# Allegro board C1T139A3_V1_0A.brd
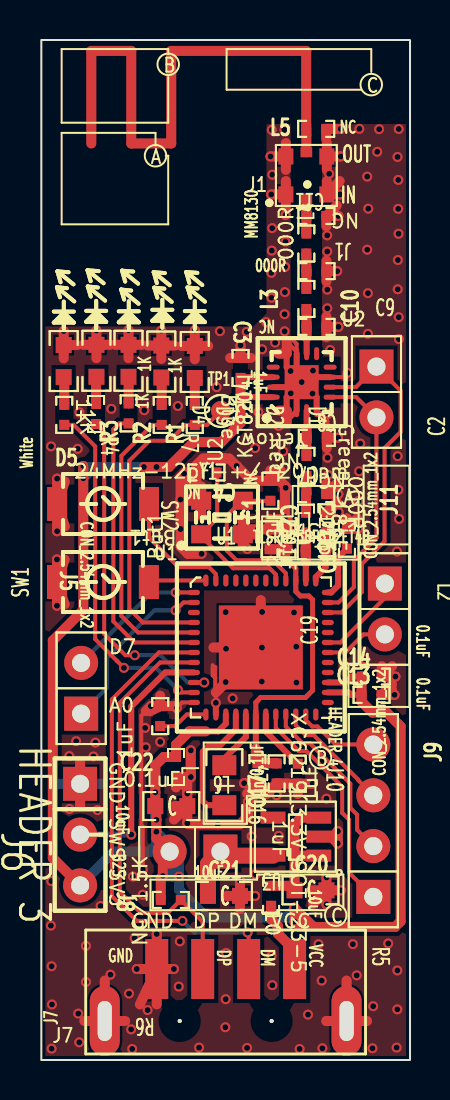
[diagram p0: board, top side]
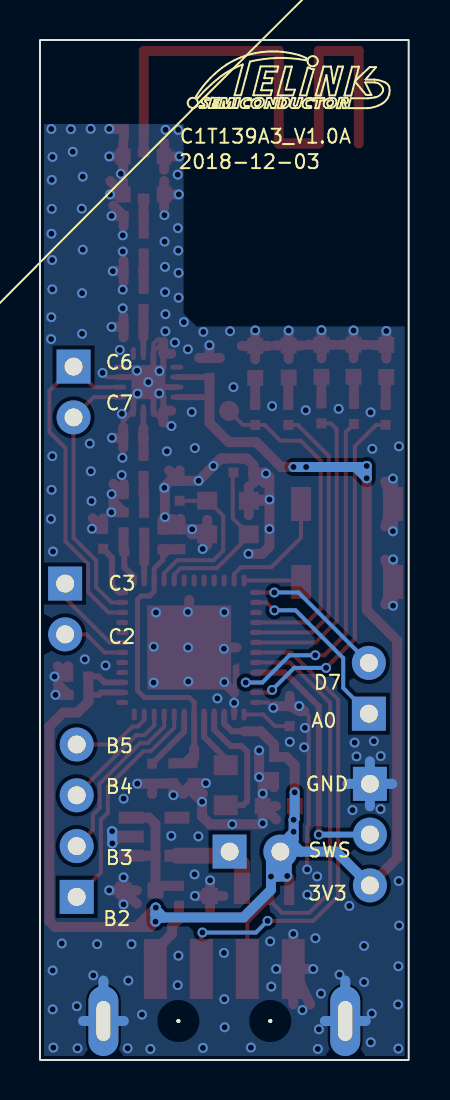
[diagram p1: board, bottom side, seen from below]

Outline 18.45 x 51 mm; copper layers: TOP, BOTTOM. Coordinates in mm from the lower left corner of the outline.
Outline path: rectangle 0,0 18.45,51

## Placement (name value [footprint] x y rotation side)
C1  NC  [0402]  11.46 28.46 90 top
C2  2.2uF  [0402]  12.31 26.03 270 top
C3  1uF  [0402]  9.97 34.6 270 top
C4  NC  [0402]  8.26 29.38 180 top
C5  18pF  [0402]  14.27 26.89 90 top
C6  220pF  [0402]  13.24 26.87 90 top
C7  NC  [0402]  13.76 28.29 180 top
C8  NC  [0402]  13.79 31.11 180 top
C9  1.5pF  [0402]  13.77 36.66 180 top
C10  1.8pF  [0402]  13.77 39.44 180 top
C11  0.5pF  [0402]  13.76 42.2 180 top
C12  1uF  [0402]  15.29 26.06 90 top
C13  0.1uF  [0402]  16.53 18.26 0 top
C14  0.1uF  [0402]  16.54 19.17 0 top
C15  1uF  [0402]  5.95 17.2 90 top
C16  1uF  [0402]  10.81 14.34 90 top
C17  0.1uF  [0402]  11.77 14.33 90 top
C18  1uF  [0402]  12.84 14.31 270 top
C19  0.1uF  [0402]  6.74 14.65 90 top
C20  10uF  [0603C]  13.47 8.48 0 top
C21  10uF  [0603C]  9.14 8.2 0 top
C22  10uF  [0603C]  6.5 12.7 0 top
C23  0.1uF  [0402]  11.42 26.04 270 top
D1  Green  [0603-LED]  7.68 34.9 90 top
D2  Red  [0603-LED]  6.01 34.92 90 top
D3  Yellow  [0603-LED]  4.36 34.96 90 top
D4  Blue  [0603-LED]  2.76 34.96 90 top
D5  White  [0603-LED]  1.12 34.95 90 top
J1  MM8130  [MM8130-2600]  13.26 44.23 180 top
J5  CON_2.54mm_1x2  [HDR254F-1X2X850]  1.99 19.86 270 top
J6  HEADER 3  [HDR254M-1X3]  1.94 13.81 270 top
J7  USB_SMT_4PIN  [USB-M-4]  9.22 4.55 90 top
J8  B2S  [HDR254F-1X2X850]  6.42 10.42 0 top
J9  CON_2.54mm_1x2  [HDR254F-1X2X850]  17.19 21.28 90 top
J10  HEADER 4  [HDR254F-1X4X850]  16.61 15.78 270 top
J11  CON_2.54mm_1x2  [HDR254F-1X2X850]  16.77 32.13 90 top
L1  1.3nH  [0402]  13.73 25.44 180 top
L2  000R  [0402]  13.27 29.71 90 top
L3  2.2nH  [0402]  13.26 38.05 90 top
L4  1.5nH  [0402]  13.26 40.82 90 top
L5  3nH  [0402]  13.75 46.56 0 top
L6  47uH  [0805L]  9.16 13.74 270 top
R1  1K  [0402]  7.68 32.25 90 top
R2  1K  [0402]  6.02 32.25 90 top
R3  1K  [0402]  4.37 32.33 90 top
R4  1K  [0402]  2.74 32.3 90 top
R5  10  [0402]  11.5 8.21 90 top
R6  NC/1.5K  [0402]  6.48 8 0 top
R7  1K  [0402]  1.15 32.26 90 top
SW1  But1  [BUTSMD2PX4_00Y3_00_NH]  3.08 23.9 270 top
SW2  But1  [BUTSMD2PX4_00Y3_00_NH]  3.09 27.8 270 top
TP1  A2  [TP100]  8.99 32.45 0 top
U1  TLSR8258F512ET48  [QFN_7X7_48PIN_0P5_4P20X4P20]  10.98 20.63 0 top
U2  KCT8204L  [QFN_3X3_16PIN_0P5_1P70X1P70]  13.03 33.89 90 top
U3  XC6219_3.3V_SOT-23-5  [SOT-23-5]  12.74 11.17 90 top
Y1  24MHz-12pF-+/-20ppm  [OSCCC200X250X080]  9.04 27.12 90 top

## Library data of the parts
C1 C4 = C1005_NC
C2 C13 C14 C23 = C1005X5R1C104K
C3 C6-C11 = C1608_NC
C5 = C1005C0G1H100D
C12 = C1608X5R1C105M
C15-C17 C19 = C1005X5R1C105K
C18 C20-C22 = C1608X5R0J106M
D1-D5 = 0603D_Red
J1 = MM8130
J5 J9 J11 = CON_2.54mm_1x2: User Part Number: pn; Tolerance: RichardLC
J6 = HEADER 3: User Part Number: pn; Tolerance: RichardLC
J7 = USB_SMT_1
J8 = B2S_0: User Part Number: pn; Tolerance: RichardLC
J10 = HEADER_4: User Part Number: pn; Tolerance: RichardLC
L1-L4 = MLK1608_000R
L5 = MLK1005S1N5ST
L6 = IND_0
R1-R4 R7 = RS0402K332JT
R5 R6 = RS0402K100JT
SW1 SW2 = SW2PIN_3x4
TP1 = TestPad100
U1 = TLSR8258F512ET48
U2 = RFX2401C_6
U3 = XC6219_1.3V_SOT-23-5
Y1 = OSC_25x32_4pin

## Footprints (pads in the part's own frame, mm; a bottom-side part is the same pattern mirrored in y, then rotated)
0402
  rect 0.5x0.5 smd: 1(-0.5,0) 2(0.5,0)
0603-LED
  rect 0.8x0.8 smd: A(-0.8,0) C(0.8,0)
0603C
  rect 0.8x0.8 smd: 1(-0.8,0) 2(0.8,0)
0805L
  rect 1x1.2 smd: 1(-1,0) 2(1,0)
BUTSMD2PX4_00Y3_00_NH
  rect 1.7x1 smd: 1(0,2.3) 2(0,-2.3)
HDR254F-1X2X850
  rect 1.7x1.7 hole 0.9: 1(2.54,0)
  round 1.7 hole 0.9: 2(0,0)
HDR254F-1X4X850
  rect 1.7x1.7 hole 0.9: 1(7.62,0)
  round 1.7 hole 0.9: 2(5.08,0) 3(2.54,0) 4(0,0)
HDR254M-1X3
  rect 1.7x1.7 hole 0.9: 1(0,0)
  round 1.7 hole 0.9: 2(2.54,0) 3(5.08,0)
MM8130-2600
  rect 0.58x0.5 smd: 1(0,1.16) 2(0,-1.16)
  rect 0.75x0.8 smd: 3(-1.025,0.95) 4(1.025,0.95) 5(-1.025,-0.95) 6(1.025,-0.95)
OSCCC200X250X080
  rect 0.9x1 smd: 1(-0.84,1.04) 2(-0.84,-1.04) 3(0.84,-1.04) 4(0.84,1.04)
QFN_3X3_16PIN_0P5_1P70X1P70
  oval 0.65x0.25 smd: 1(-1.425,0.75) 2(-1.425,0.25) 3(-1.425,-0.25) 4(-1.425,-0.75) 9(1.425,-0.75) 10(1.425,-0.25) 11(1.425,0.25) 12(1.425,0.75)
  oval 0.25x0.65 smd: 5(-0.75,-1.425) 6(-0.25,-1.425) 7(0.25,-1.425) 8(0.75,-1.425) 13(0.75,1.425) 14(0.25,1.425) 15(-0.25,1.425) 16(-0.75,1.425)
  rect 1.7x1.7 smd: 17(0,0)
QFN_7X7_48PIN_0P5_4P20X4P20
  oval 0.6x0.26 smd: 1(-3.35,2.75) 2(-3.35,2.25) 3(-3.35,1.75) 4(-3.35,1.25) 5(-3.35,0.75) 6(-3.35,0.25) 7(-3.35,-0.25) 8(-3.35,-0.75) 9(-3.35,-1.25) 10(-3.35,-1.75) 11(-3.35,-2.25) 12(-3.35,-2.75) 25(3.35,-2.75) 26(3.35,-2.25) 27(3.35,-1.75) 28(3.35,-1.25) 29(3.35,-0.75) 30(3.35,-0.25) 31(3.35,0.25) 32(3.35,0.75) 33(3.35,1.25) 34(3.35,1.75) 35(3.35,2.25) 36(3.35,2.75)
  oval 0.26x0.6 smd: 13(-2.75,-3.35) 14(-2.25,-3.35) 15(-1.75,-3.35) 16(-1.25,-3.35) 17(-0.75,-3.35) 18(-0.25,-3.35) 19(0.25,-3.35) 20(0.75,-3.35) 21(1.25,-3.35) 22(1.75,-3.35) 23(2.25,-3.35) 24(2.75,-3.35) 37(2.75,3.35) 38(2.25,3.35) 39(1.75,3.35) 40(1.25,3.35) 41(0.75,3.35) 42(0.25,3.35) 43(-0.25,3.35) 44(-0.75,3.35) 45(-1.25,3.35) 46(-1.75,3.35) 47(-2.25,3.35) 48(-2.75,3.35)
  rect 4.2x4.2 smd: 49(0,0)
SOT-23-5
  rect 0.6x1.25 smd: 1(-0.95,-1.145) 2(0,-1.145) 3(0.95,-1.145) 4(0.95,1.145) 5(-0.95,1.145)
TP100
  round 1 smd: 1(0,0)
USB-M-4
  round 0.2 hole 1.7 unplated: (-2.6,2.3) (-2.6,-2.3)
  rect 3x1.15 smd: 1(0,-3.45) 2(0,-1.15) 3(0,1.15) 4(0,3.45)
  oval 3.5x1.5 hole 2x0.7: S1(-2.6,6.05) S2(-2.6,-6.05)

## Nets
3V3: C3.2 C13.1 C14.1 C19.2 C22.1 J6.3 J8.2 R6.1 U1.15(VDD_IO) U1.26(VDD3) U1.27(VDDIO_AMS) U2.14(VDD#14) U2.16(VDD#16)
GND: C1.2 C2.1 C3.1 C4.2 C5.2 C7.1 C8.1 C9.1 C10.1 C11.1 C12.2 C13.2 C14.2 C15.2 C16.1 C17.1 C18.2 C19.1 C20.2 C21.2 C22.2 C23.1 D1.C(CATHODE) D2.C(CATHODE) D3.C(CATHODE) D4.C(CATHODE) D5.C(CATHODE) J1.3 J1.4 J1.5 J1.6 J6.1 J7.4(GND) J7.S1 J7.S2 L5.2 SW1.2 SW2.2 U1.12(DVSS#12) U1.14(DVSS#14) U1.49(GND) U2.1(BYPASS) U2.2(GND#2) U2.4(GND#4) U2.7(GND#7) U2.11(ANT_SEL) U2.12(GND#12) U2.15(GND#15) U2.17(GND#17) U3.2(VSS) Y1.2 Y1.4
VBUS: C20.1 R5.2 U3.1(VIN) U3.3(CE)
TL_1V2: C2.2 C16.2 C17.2 C23.2 U1.18(VDD1V2) U1.39(AVDD1V2)
TL_A0: J5.1 U1.2(DMIC_DI/P0N/URX/A[0])
TL_A2: R1.1 TP1.1(TP) U1.4(DO/UTX/P0/A[2])
TL_A3: R2.1 U1.5(DI/UCTS/P1/A[3])
TL_A4: R3.1 U1.6(CK/URTS/P2/A[4])
TL_ANT: C6.1 L1.2 U1.38(ANT)
TL_B0: R4.1 U1.10(P3/URX/ATSEL1/B[0])
TL_B1: R7.1 U1.11(P4/UTX/ATSEL2/B[1])
TL_B2: J10.1 U1.20(P5/UCTS/CYC2LNA/B[2])
TL_B3: J10.2 U1.21(P0N/URTS/CYC2PA/B[3])
TL_B4: J10.3 U1.22(SDMP0/P4/B[4])
TL_B5: J10.4 U1.23(SDMN0/P5/B[5])
TL_C2: J9.2 U1.30(P0/7816TRX/I2CSDA/32KO/PGAP1/C[2])
TL_C3: J9.1 U1.31(P1/URX/I2CCK/32KI/PGAN1/C[3])
TL_C6: J11.1 U1.34(CYC2LNA/ATSEL1/P4N/C[6]) U2.6(RXEN)
TL_C7: J11.2 U1.35(CYC2PA/ATSEL2/P5N/C[7]) U2.5(TXEN)
TL_D5: SW2.1 U1.47(P0/P0N/D[5])
TL_D6: SW1.1 U1.48(CN/URX/ATSEL0/D[6])
TL_D7: J5.2 U1.1(CK/I2SBCK/7816TRX/D[7])
TL_DM: J7.2(D-) U1.7(DM/A[5])
TL_DP: J7.3(D+) R6.2 U1.8(DP/A[6])
TL_SWS/A7: J6.2 U1.9(SWS/URTS/A[7])
TL_XC1: C1.1 U1.40(XC1) Y1.3
TL_XC2: C4.1 U1.41(XC2) Y1.1
N14798367: C18.1 U1.19(VDD_F)
N14798471: L6.1 U1.17(VDCDC)
N14798499: L6.2 U1.16(VDCDC_SW)
N14798557: C15.1 U1.13(VDD1V)
N14798729: C12.1 U1.36(RESETB)
N14798779: C5.1 L1.1 U1.37(VANT)
N14803016: C6.2 C7.2 L2.1
N14803042: C8.2 L2.2 U2.3(TXRX)
N14803152: C10.2 L3.2 L4.1
N14803180: C9.2 L3.1 U2.10(ANT1)
N14803220: C11.2 J1.1 L4.2
N14803264: J1.2 L5.1
N14807404: D1.A(ANODE) R1.2
N14807456: D3.A(ANODE) R3.2
N14807480: D4.A(ANODE) R4.2
N14807598: D2.A(ANODE) R2.2
N14823075: C21.1 J8.1 U3.5(VOUT)
N14823079: J7.1(5V) R5.1
N14826545: D5.A(ANODE) R7.2

Pads without a net: U1 3 24 25 28 29 32 33 42 43 44 45 46; U2 8 9 13; U3 4

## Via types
v1: diameter 0.5, hole 0.3, TOP to BOTTOM, 210 vias

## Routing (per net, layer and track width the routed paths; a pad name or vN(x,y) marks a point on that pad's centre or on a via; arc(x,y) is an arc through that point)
3V3: length 99.7
  TOP w0.3: 9.97,33.12 9.99,33.14 U2.16 ; U2.14 10.01,34.14 C3.2 ; U1.27 15.22,18.88 15.52,19.17 C14.1 ; U1.15 9.23,16.82 8.85,16.43 8.22,16.43 ; U1.26 15.39,18.38 15.51,18.26 C13.1
  TOP w0.5: C14.1 16.03,19.16 C13.1 16.03,17.92 16.57,17.37 17.29,17.37 17.98,16.68 17.98,6.94 17.7,6.65 13.62,6.65 ; 13.62,6.65 12.93,6.65 v1(12.67,6.92) 12.67,7.6 ; 13.62,6.65 12.67,7.6 ; 12.67,7.6 v1(12.65,7.62) ; C3.2 9.97,31.86 9.01,30.89 7.63,30.89 6.38,29.65 v1(5.76,29.65) v1(5.13,29.65) ; J6.3 0.58,10.09 0.58,20.97 2.1,22.5 v1(2.1,29.09) v1(2.1,29.7) ; 8.22,16.43 7.4,16.43 6.74,15.77 C19.2 6.12,15.15 5.7,14.73 v1(5.7,13.39) C22.1 5.76,12.64 v1(5.76,12.01) v1(5.76,11.41) 5.76,11.08 J8.2 6.08,10.08 v1(6.08,9.2) 5.98,9.1 R6.1
  BOTTOM w0.5: 5.76,11.39 5.76,11.08 ; 5.76,11.39 6.42,10.73 J8.2 ; 5.76,11.39 v1(5.76,11.41) v1(5.76,12.01) 5.7,12.06 v1(5.7,13.39) ; 5.76,11.08 5.76,10.76 5.41,10.42 ; 5.76,11.08 J8.2 ; 6.11,9.17 6.58,9.17 ; 6.11,9.17 6.11,10.11 J8.2 ; 6.11,9.17 v1(6.08,9.2) ; 6.58,9.17 6.42,9.33 J8.2 ; 6.58,9.17 v1(6.89,9.17) ; 2.66,29.65 v1(2.1,29.09) v1(2.1,29.7) 2.15,29.65 2.66,29.65 ; 2.66,29.65 v1(5.13,29.65) v1(5.76,29.65) ; v1(6.89,9.17) 6.89,8.51 8.27,7.13 12.27,7.13 ; v1(6.89,9.17) 6.89,9.95 J8.2 ; 12.27,7.13 12.46,7.13 v1(12.67,6.92) 12.67,7.29 ; 12.27,7.13 12.51,7.37 ; 5.41,10.42 3.63,10.42 J6.3 ; 5.41,10.42 J8.2 ; 12.67,7.29 12.6,7.29 12.51,7.37 ; 12.67,7.29 12.67,7.6 v1(12.65,7.62) 12.65,7.51 12.51,7.37
GND: length 173.8
  TOP w0.2: U1.12 7.04,17.88 v1(6.77,17.61) ; v1(15.32,34.35) 15.11,34.14 U2.7 ; U2.11 12.78,35.41 ; 12.78,35.41 12.78,35.81 12.53,36.05 ; 12.78,35.41 12.28,35.91 ; 8.69,19.66 8.7,19.65 8.7,19.1 ; 8.7,19.1 8.7,18.41 8.73,18.38 v1(8.73,17.86) ; 8.7,19.1 8.57,19.23 8.57,19.74 ; 5.23,17.44 5,17.22 5,11.74 5.08,11.66 v1(5.08,9.53)
  TOP w0.25: U2.2 12.78,32.45 12.28,31.95 ; U2.4 13.79,32.47 14.29,31.97 14.29,31.63
  TOP w0.3: U2.11 12.78,34.14 ; 12.78,34.14 12.28,34.64 U2.12 ; 12.78,34.14 U2.17 ; U1.14 v1(8.73,17.86) ; U2.4 13.78,33.14 U2.17 ; U2.17 13.28,34.14 U2.7 ; U2.17 12.78,33.64 ; U2.1 12.28,33.14 12.78,33.64 ; U2.15 12.78,33.64 ; 12.78,33.64 U2.2
  TOP w0.5: C21.2 v1(9.94,8.98) ; C21.2 9.94,7.53 ; C21.2 9.27,8.2 ; C21.2 v1(10.7,8.2) ; C23.1 11.43,26.53 C2.1 ; C23.1 11.94,27.06 ; C23.1 v1(10.83,26.54) 10.33,26.54 Y1.2 ; C23.1 11.42,27.06 ; J1.6 v1(11.47,45.18) ; J1.6 12.24,45.85 ; J1.6 12.24,44.51 ; C18.2 v1(13.58,13.81) ; C18.2 12.32,13.81 ; C18.2 12.84,13.29 ; 8,27.24 Y1.4 ; Y1.4 7.23,27.96 ; Y1.4 8,28.68 ; Y1.4 7.94,28.02 v1(6.97,28.02) ; v1(7.48,14.15) 7.3,13.97 v1(7.3,13.32) C22.2 ; v1(7.48,14.15) v1(7.48,15.48) ; v1(7.48,14.15) C19.1 ; SW2.2 1.18,28.92 ; SW2.2 v1(0.79,29.07) ; SW2.2 1.18,26.68 ; SW2.2 v1(0.79,26.44) ; 6.63,12.02 C22.2 ; C22.2 v1(7.3,11.84) 7.35,11.79 v1(8.83,11.79) 9.95,11.79 10.34,12.18 v1(10.34,12.91) 10.81,13.39 C16.1 ; C22.2 6.63,12.7 ; Y1.2 10.08,25.78 v1(10.31,25.55) ; Y1.2 10.85,26.28 ; Y1.2 10.08,27 ; SW1.2 v1(0.78,22.71) ; SW1.2 1.17,22.78 ; SW1.2 1.17,25.02 ; SW1.2 v1(0.78,25.03) ; D4.C v1(2.76,36.48) ; D4.C 2.76,35.09 ; D4.C 2.09,35.76 ; D4.C 3.43,35.76 ; v1(6.97,28.02) v1(6.97,26.55) 6.97,25.68 7.33,25.31 v1(8.02,25.31) ; v1(6.97,28.02) 6.97,29.15 v1(7.14,29.32) 7.2,29.38 C4.2 ; C5.2 14.79,27.91 ; C5.2 14.79,27.65 ; C5.2 v1(14.88,27.39) ; 6.01,35.05 D2.C ; D2.C 6.68,35.72 ; D2.C v1(6.01,36.47) ; D2.C 5.34,35.72 ; C9.1 14.27,37.18 ; C9.1 14.27,36.14 ; C9.1 v1(14.87,36.66) ; C2.1 12.05,27.05 ; C2.1 12.31,27.02 12.2,27.13 v1(12.2,27.15) 12.2,28.46 12.23,28.5 v1(12.23,28.61) 12.23,28.67 11.94,28.96 C1.2 ; C2.1 11.79,27.05 ; 13.6,8.48 C20.2 ; C20.2 13.6,7.81 ; C20.2 v1(14.27,7.78) ; C20.2 v1(14.27,9.13) ; C20.2 v1(14.99,8.48) ; 6.74,13.63 C19.1 ; C19.1 7.26,13.63 ; 7.76,28.86 C4.2 ; C4.2 7.24,28.86 ; C4.2 7.76,29.74 8.1,30.07 8.32,30.07 8.33,30.08 9.2,30.08 9.2,30.07 9.4,30.07 v1(9.77,29.7) v1(10.52,28.96) C1.2 ; 1.12,35.08 D5.C ; D5.C 1.79,35.75 ; D5.C v1(1.12,36.45) ; C1.2 11.46,29.48 ; C1.2 11.98,29.48 ; 5.78,4.55 v1(5.78,6.3) ; 5.78,4.55 5.78,2.78 ; 5.78,4.55 v1(4.78,4.55) ; 5.78,4.55 4.93,2.78 ; 5.78,4.55 v1(6.63,4.55) ; 3.69,35.76 D3.C ; D3.C 5.03,35.76 ; D3.C 4.36,35.09 ; D3.C v1(4.36,36.49) ; 14.29,44.51 J1.5 ; J1.5 v1(14.98,45.18) ; J1.5 14.29,45.85 ; C14.2 v1(17.72,19.17) ; C14.2 17.04,19.69 ; C14.2 17.56,19.69 ; D1.C 8.35,35.7 ; D1.C 7.01,35.7 ; D1.C 7.68,35.03 ; D1.C v1(7.68,36.48) ; C13.2 v1(17.67,18.26) ; C13.2 17.55,18.52 ; C13.2 17.55,18.78 ; C10.1 v1(14.8,39.44) ; C10.1 14.27,39.96 ; C10.1 14.27,38.92 ; J1.3 14.93,43.95 ; J1.3 v1(14.95,43.28) ; J1.3 14.29,43.95 ; C15.2 v1(5.48,17.7) 5.23,17.44 ; C15.2 5.95,18.22 ; C15.2 6.69,17.7 v1(6.77,17.61) ; C15.2 5.43,17.43 ; C16.1 v1(10.15,13.84) ; C16.1 11.34,13.32 ; C16.1 10.29,13.32 ; C7.1 v1(14.86,28.29) ; C7.1 14.26,28.81 ; C7.1 14.78,28.81 ; 14.29,30.59 C8.1 ; C8.1 v1(14.85,31.11) ; C8.1 14.29,31.63 ; 2.15,1.95 J7.S1 ; J7.S1 4.2,1.95 ; J7.S1 3.17,3.97 ; 11.25,13.31 C17.1 ; C17.1 v1(11.77,13.24) ; C17.1 12.29,13.83 ; C11.1 v1(14.86,42.2) ; C11.1 14.26,41.68 ; C11.1 14.78,42.72 ; 1.94,14.93 J6.1 1.94,12.69 ; 14.25,46.04 L5.2 v1(14.98,46.56) ; 11.88,32.47 U2.1 12.28,31.87 ; 8.61,20.63 U1.49 ; U1.49 8.73,18.38 ; U1.49 10.98,23 ; 14.83,11.43 14.57,11.17 14.49,11.17 ; 14.83,11.43 v1(14.83,10.83) 14.49,11.17 ; 14.83,11.43 v1(14.84,11.44) ; 15.28,1.95 16.3,1.95 ; 15.28,1.95 15.28,3.97 ; 15.28,1.95 14.25,1.95 ; C12.2 15.29,27.08 ; C12.2 v1(15.85,26.56) ; C12.2 15.81,27.08 ; U3.2 14.49,11.17 ; 9.45,35.1 C3.1 ; C3.1 10.49,35.1 ; C3.1 v1(9.97,35.74) ; 12.28,35.91 U2.12 11.88,35.32 ; 12.24,42.61 J1.4 ; J1.4 v1(11.5,43.28) ; J1.4 12.24,43.95
  BOTTOM w0.5: v1(14.83,10.83) 14.83,11.43 v1(14.84,11.44) ; 15.28,1.95 15.28,3.97 ; 15.28,1.95 14.25,1.95 ; 15.28,1.95 16.3,1.95 ; J7.S1 3.17,3.97 ; J7.S1 2.15,1.95 ; J7.S1 4.2,1.95 ; 1.94,12.69 J6.1 ; J6.1 0.82,13.81 ; J6.1 1.94,14.93 ; J6.1 3.06,13.81
  vias: v1(0.49,30.68) v1(0.5,8.95) v1(0.48,6.72) v1(0.51,4.69) v1(0.53,2.78) v1(0.51,0.57) v1(1.4,15.2) v1(1.41,12.55) v1(1.74,15.94) v1(1.82,30.56) v1(1.85,2.32) v1(1.91,32.38) v1(1.9,0.88) v1(2.23,5.7) v1(2.23,3.9) v1(2.61,15.18) v1(2.71,15.87) v1(2.81,12.5) v1(2.97,7.7) v1(3.5,32.56) v1(3.46,4.27) v1(4.39,3.32) v1(4.49,1.53) v1(4.55,0.55) v1(4.58,9.18) v1(4.67,6.09) v1(5.07,8.26) v1(5.15,32.49) v1(5.19,16.61) v1(5.23,15.63) v1(5.32,2.5) v1(5.95,15.91) v1(6.83,32.7) v1(6.93,5.93) v1(6.88,3.67) v1(7.89,0.62) v1(8.77,33.64) v1(8.94,36.44) v1(9.23,22.39) v1(9.24,20.56) v1(9.23,18.9) v1(9.24,5.35) v1(9.23,3.04) v1(9.21,1.64) v1(9.57,18.08) v1(10.28,36.41) v1(10.3,0.6) v1(10.52,11.18) v1(10.7,30.59) v1(10.72,9.28) v1(10.86,32.4) v1(11.05,35.54) v1(11.05,22.4) v1(11.04,20.62) v1(11.03,18.92) v1(11.25,36.9) v1(11.53,46.51) v1(11.55,41.59) v1(11.53,40.47) v1(11.51,39.36) v1(11.51,38.11) v1(11.52,5.21) v1(11.56,44.27) v1(11.56,3.74) v1(11.7,35.87) v1(11.87,31.7) v1(11.88,11.21) v1(12.1,30.44) v1(12.17,46.51) v1(12.22,42.24) v1(12.21,40.92) v1(12.2,39.66) v1(12.19,38.39) v1(12.17,37.29) v1(12.18,36.44) v1(12.47,34.45) v1(12.48,33.33) v1(12.64,22.38) v1(12.76,20.67) v1(12.77,18.87) v1(12.92,0.55) v1(13.03,33.9) v1(13.35,2.27) v1(13.59,34.47) v1(13.57,33.32) v1(13.87,5.79) v1(14.03,3.97) v1(14.06,0.59) v1(14.31,41.23) v1(14.31,40.42) v1(14.31,38.52) v1(14.31,37.58) v1(14.35,32.31) v1(14.32,30.11) v1(14.27,13.07) v1(14.4,44.31) v1(14.36,29.25) v1(14.46,35.5) v1(15.17,19.73) v1(15.59,5.79) v1(15.78,4.23) v1(15.91,46.56) v1(15.9,29.44) v1(15.87,27.95) v1(15.96,30.82) v1(16.21,20.03) v1(16.31,44.17) v1(16.31,40.52) v1(16.34,38.34) v1(16.34,36.31) v1(16.36,42.57) v1(16.61,2.69) v1(16.57,0.59) v1(16.81,45.41) v1(16.9,46.54) v1(17.36,5.83) v1(17.82,45.15) v1(17.84,40) v1(17.83,38.53) v1(17.83,30.19) v1(17.8,25.42) v1(17.82,4.48) v1(17.82,2.53) v1(17.78,0.62) v1(17.89,46.55) v1(17.86,44) v1(17.86,42.56) v1(17.88,41.31) v1(17.89,37.14) v1(17.89,36.05) v1(17.87,28.51) v1(17.9,27.05)
VBUS: length 7.1
  TOP w0.5: R5.2 12.44,8.71 C20.1 12.67,10.22 ; U3.1 12.67,10.22 ; 12.67,10.22 12.67,11.79 13,12.12 13.88,12.12 U3.3
TL_1V2: length 17.6
  TOP w0.25: 12.31,25.11 12.31,24.99 12.73,24.57 U1.39 12.73,23.43 12.96,23.2 13.39,23.2 13.57,23.02 13.57,18.48 13.22,18.13 10.98,18.13 10.73,17.88 U1.18 ; 12.31,25.11 11.89,25.54 ; 12.31,25.11 C2.2
  TOP w0.3: U1.18 10.73,15.57 ; C16.2 10.73,15.27
  TOP w0.5: 11.17,14.84 11.76,14.84 C17.2 ; 11.17,14.84 10.98,14.84 10.98,14.84 ; 11.17,14.84 10.73,15.27 ; 10.73,15.57 10.73,15.27 ; 10.73,15.27 10.73,15.09 10.98,14.84 ; 10.98,14.84 C16.2 ; C2.2 12.3,25.54 C23.2
TL_A0: length 8.8
  TOP w0.2: v1(6.72,22.48) 7.11,22.88 U1.2
  BOTTOM w0.2: v1(6.72,22.48) 5.66,22.48 3.28,20.1 3.28,18.6 J5.1
TL_A2: length 16.5
  TOP w0.2: U1.4 5.08,21.88 4.4,22.55 4.4,29.96 5.4,30.96 6.42,30.96 7.21,31.75 R1.1 8.29,31.75 TP1.1
TL_A3: length 14.6
  TOP w0.2: R2.1 5.55,31.75 4,30.21 4,22.21 4.83,21.38 U1.5
TL_A4: length 15
  TOP w0.2: R3.1 3.9,31.83 3.6,31.54 3.6,21.93 4.66,20.88 U1.6
TL_ANT: length 2.4
  TOP w0.3: U1.38 13.23,24.88
  TOP w0.5: 13.23,24.88 13.23,25.44 L1.2 13.23,26.35 C6.1
TL_B0: length 17.2
  TOP w0.2: R4.1 3.15,31.4 3.15,21.3 4.21,20.24 v1(4.68,20.24) ; U1.10 v1(8.15,18.88)
  BOTTOM w0.2: v1(8.15,18.88) 7.32,18.88 5.96,20.24 v1(4.68,20.24)
TL_B1: length 17.7
  TOP w0.2: v1(4.13,19.61) 3.8,19.94 2.7,21.04 2.7,30.68 1.62,31.76 R7.1 ; U1.11 6.96,18.38 v1(6.83,18.5)
  BOTTOM w0.2: v1(4.13,19.61) 5.73,19.61 v1(6.83,18.5)
TL_B2: length 11.4
  TOP w0.2: U1.20 11.73,16.61 12.9,15.44 13.27,15.44 15.05,13.66 15.05,12.36 15.4,12.01 15.4,11.34 15.4,11.34 15.4,9.36 J10.1
TL_B3: length 8.6
  TOP w0.2: J10.2 15.8,11.51 15.8,12.27 15.46,12.61 15.46,13.82 13.44,15.84 13.06,15.84 12.23,16.67 U1.21
TL_B4: length 5.9
  TOP w0.2: J10.3 15.86,13.99 15.86,14.02 13.63,16.24 13.23,16.24 12.73,16.74 U1.22
TL_B5: length 4.2
  TOP w0.2: U1.23 13.23,17 13.56,16.68 13.82,16.68 14.72,15.78 J10.4
TL_C2: length 3.2
  TOP w0.2: U1.30 15.22,20.38 16.12,21.28 J9.2
TL_C3: length 4.5
  TOP w0.2: J9.1 17.19,23.1 14.96,20.88 U1.31
TL_C6: length 17.5
  TOP w0.2: U2.6 15.74,33.64 J11.1 17.98,33.46 17.98,31.4 17.17,30.6 17.17,25.93 16.04,24.8 16.04,23.4 15.02,22.38 U1.34
TL_C7: length 13.3
  TOP w0.2: U1.35 14.87,22.88 15.64,23.65 15.64,24.98 16.77,26.11 J11.2 15.76,33.14 U2.5
TL_D5: length 6.1
  TOP w0.2: U1.47 8.73,24.3 8.39,24.64 6.87,24.64 5.39,26.12 SW2.1
TL_D6: length 2.9
  TOP w0.2: U1.48 5.46,23.98 SW1.1
TL_D7: length 7.1
  TOP w0.2: v1(6.72,23.38) U1.1
  BOTTOM w0.2: v1(6.72,23.38) 5.51,23.38 J5.2
TL_DM: length 24.3
  TOP w0.2: v1(10.32,6.37) 10.38,6.32 J7.2 ; v1(7.06,6.96) 4.77,6.96 3.53,8.2 3.53,18.03 5.88,20.38 U1.7
  BOTTOM w0.2: v1(10.32,6.37) 7.64,6.37 v1(7.06,6.96)
TL_DP: length 21.7
  TOP w0.2: U1.8 5.95,19.88 3.93,17.86 3.93,8.4 4.97,7.36 6.33,7.36 R6.2 8.07,6.91 J7.3
TL_SWS/A7: length 12.8
  TOP w0.3: v1(4.5,11.27) 4.5,17.68 6.2,19.38 U1.9
  BOTTOM w0.3: J6.2 v1(4.5,11.27)
TL_XC1: length 8
  TOP w0.2: C1.1 10.81,27.96 10.8,27.96 Y1.3 10.03,27.96 9.28,27.21 9.28,25.47 9.76,24.99 11.59,24.99 12.23,24.34 U1.40
TL_XC2: length 8.4
  TOP w0.2: C4.1 8.8,29.34 8.8,27.08 Y1.1 8,26.18 9.6,24.59 11.42,24.59 11.73,24.27 U1.41
N14798367: length 3.1
  TOP w0.3: C18.1 11.23,16.42 U1.19
N14798471: length 3
  TOP w0.3: L6.1 9.16,15.08 9.64,15.56 10.23,16.15 U1.17
N14798499: length 6.5
  TOP w0.3: U1.16 9.73,16.52 8.91,15.7 8.37,15.7 8.08,15.41 8.08,12.95 8.29,12.74 L6.2
N14798557: length 2.5
  TOP w0.2: U1.13 7.28,17.28 6.7,16.7 C15.1
N14798729: length 2.7
  TOP w0.3: C12.1 14.85,25.12 14.85,23.72 14.5,23.38 U1.36
N14798779: length 2.6
  TOP w0.3: U1.37 13.73,24.15 14.23,24.64 L1.1
  TOP w0.5: L1.1 14.27,25.48 C5.1
N14803016: length 1.8
  TOP w0.5: L2.1 13.27,28.31 C7.2 13.24,28.28 C6.2
N14803042: length 2.3
  TOP w0.3: U2.3 13.28,31.58
  TOP w0.5: 13.28,31.58 13.28,31.12 C8.2 13.27,31.09 L2.2
N14803152: length 1.8
  TOP w0.5: L3.2 13.26,39.44 C10.2 13.26,39.45 L4.1
N14803180: length 2.2
  TOP w0.3: 13.28,36.13 U2.10
  TOP w0.5: L3.1 13.27,37.55 C9.2 13.28,36.65 13.28,36.13
N14803220: length 1.7
  TOP w0.5: J1.1 13.26,43.07 C11.2 13.26,42.2 L4.2
N14803264: length 29.7
  TOP w0.5: 2.5,45.83 2.5,50.45 4.5,50.45 4.5,45.83 6.5,45.83 6.5,50.45 13.25,50.45 L5.1 13.26,46.25 J1.2
N14807404: length 1.3
  TOP w0.5: R1.2 7.68,32.76 D1.A
N14807456: length 1.3
  TOP w0.5: D3.A 4.37,34.15 R3.2
N14807480: length 1.4
  TOP w0.5: D4.A 2.74,34.14 R4.2
N14807598: length 1.4
  TOP w0.5: R2.2 6.02,34.1 D2.A
N14823075: length 5.2
  TOP w0.8: C21.1 8.34,9.8 J8.1 9.16,10.22 U3.5
N14823079: length 3.6
  TOP w0.5: R5.1 11.5,7.04 11.84,6.7 11.84,6.31 12.68,5.47 J7.1
N14826545: length 1.4
  TOP w0.5: R7.2 1.15,34.12 D5.A

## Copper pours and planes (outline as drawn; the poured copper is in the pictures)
GND on TOP: 0.2,0.2 0.2,36.68 10.62,36.68 11.27,37.33 11.27,46.8 12.48,46.8 12.48,24.01 13.12,23.37 14.05,24.3 14.05,36.06 14.05,46.8 18.25,46.8 18.25,0.2 ; 14 cut-outs
GND on BOTTOM: 0.2,0.2 0.2,36.68 10.62,36.68 11.27,37.33 11.27,46.8 18.25,46.8 18.25,0.2

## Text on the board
Ref Des/Silkscreen Bottom: D7 | A0 | SWS | 3V3 | GND | C1T139A3_V1.0A | 2018-12-03 | C3 | C2 | C6 | C7 | B5 | B4 | B3 | B2
Ref Des/Silkscreen Top: A | B | C | D7 | A0 | GND | SWS | 3V3
COMPVAL_TYPE_TOP: B | 1.5pF | A
User.6: FIGURE | SIZE | 0.3 | 0.9 | 1.7 | 2.0x0.7 | DRILL CHART: TOP to BOTTOM | ALL UNITS ARE IN MILLIMETERS | PLATED | NON-PLATED | QTY | 210 | 15 | 2
